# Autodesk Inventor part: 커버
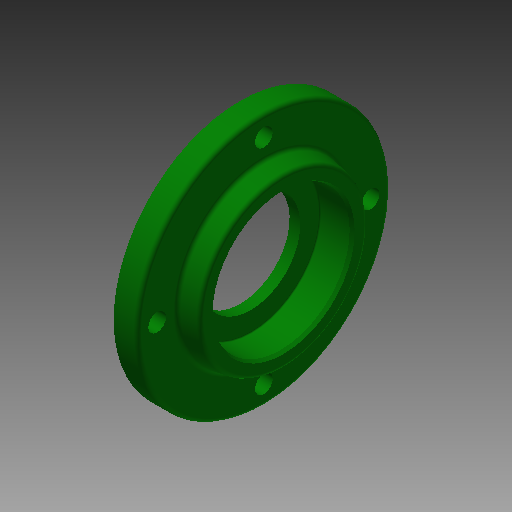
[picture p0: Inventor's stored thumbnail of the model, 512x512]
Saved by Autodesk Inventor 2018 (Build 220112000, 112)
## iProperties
Created: 2018-11
Part Number: 커버
Material: 알루미늄 6061
Document SubType Name: Modeling
Designer: mduedu
Density: 1 g/cm^3
Appearance: 진녹색
Author: mduedu
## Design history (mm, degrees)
sketch "스케치1"
  geometry: L1 (0, 0)-(3, 0); L2 (3, 0)-(3, 23.5); L3 (3, 23.5)-(0, 23.5); L4 (0, 23.5)-(0, 0); L5 (3, 0)-(9, 0); L6 (9, 0)-(9, 32); L7 (9, 32)-(3, 32); L8 (3, 32)-(3, 0); L9 (9, 0)-(14, 0); L10 (14, 0)-(14, 21.118); L11 (9, 22)-(9, 0); L12 (9, 22)-(14, 21.118)
  constraints: 24 end point, 5 parallel, 3 horizontal, 3 perpendicular
  dimensions: "d0" = 64 diameter of L7 L5; "d3" = 47 diameter of L3 L1; "d4" = 3 distance of L2.end L3.end; "d5" = 6 distance of L6.end L7.end; "d6" = 14 distance between parallel lines of L10 L4; "d37" = 44 diameter of L11.start L9; "d38" = 10 deg angle of L9 L12
revolve "회전1" sketch "스케치1" stored, may be unused: angle "d7" = 90 deg
sketch "스케치2"
  geometry: L1 (0, -23.5)-(0, 23.5) reference; L2 (0, 23.5)-(3, 23.5) reference; L3 (3, 23.5)-(3, 32) reference; L4 (3, 32)-(9, 32) reference; L5 (9, 32)-(9, 22) reference; L6 (9, -22)-(9, -32) reference; L7 (9, -32)-(3, -32) reference; L8 (3, -32)-(3, -23.5) reference; L9 (3, -23.5)-(0, -23.5) reference; L10 (0, 0)-(3, 0); L11 (3, 0)-(3, 20); L12 (3, 20)-(0, 20); L13 (0, 20)-(0, 0); L14 (3, 0)-(5.7, 0); L15 (5.7, 0)-(5.7, 12.5); L16 (5.7, 12.5)-(3, 12.5); L17 (3, 12.5)-(3, 0); L18 (5.7, 0)-(14, 0); L19 (14, 0)-(14, 17.5); L20 (14, 17.5)-(5.7, 17.5); L21 (5.7, 17.5)-(5.7, 0); L22 (9, 22)-(14, 21.118) reference; L23 (14, 21.118)-(14, -21.118) reference; L24 (14, -21.118)-(9, -22) reference
  constraints: 24 end point, 6 parallel, 3 horizontal, 3 perpendicular, 1 midpoint
  dimensions: "d8" = 35 diameter of L20 L18; "d10" = 25 diameter of L16 L14; "d11" = 40 diameter of L12 L10; "d12" = 3 distance of L11.end L12.end; "d13" = 8.3 distance of L19.end L20.end
revolve "회전2" sketch "스케치2" stored, may be unused: angle "d14" = 90 deg
fillet "모깎기1" dims "d15" = 0.3
chamfer "모따기1" distance "d16" = 0.8; stored, may be unused: second distance "d17" = 2, angle "d18" = 30 deg
fillet "모깎기2" dims "d19" = 1, "d35" = 3
chamfer "모따기2" distance "d20" = 0.5; stored, may be unused: second distance "d21" = 2, angle "d22" = 30 deg
sketch "스케치3" dims "d23" = 52
  geometry: 6 further points
  constraints: 2 vertical alignment, 1 coincident, 7 other
  dimensions: "d26" = 360 deg dimension on point (0, 0) point (0, 26) (derived)
sketch "스케치4" dims "d39" = 54
  geometry: C1 r 32 at (0, 0) reference; 5 further points
  constraints: 2 vertical alignment, 1 coincident, 7 other
  dimensions: "d43" = 360 deg dimension on C1.centre point (0, 27) (derived)
hole "구멍1" sketch "스케치4" at (0, 27), (-27, 0), (0, -27), (27, 0) diameter "d28" = 4.5; stored, may be unused: countersink angle "d32" = 90 deg, drill point angle "d34" = 0 deg; dims "d29" = 6, "d30" = 8, "d31" = 4.6, "d33" = 8
node "솔리드1"
node "절단 모서리 투영1"
